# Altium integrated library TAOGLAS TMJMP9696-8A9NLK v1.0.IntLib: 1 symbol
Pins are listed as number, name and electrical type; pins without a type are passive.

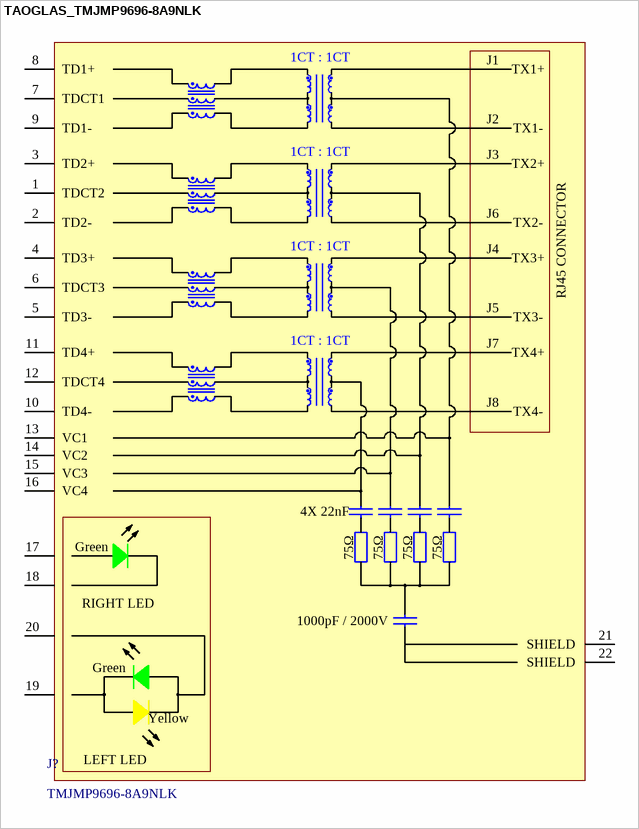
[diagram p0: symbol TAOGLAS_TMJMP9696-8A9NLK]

## TAOGLAS_TMJMP9696-8A9NLK
designator J?, comment TMJMP9696-8A9NLK
RJ45 connector with integrated magnetics 10G Base-T Single Port Tab-UP with right angle THT mount and LED; ComponentLibStatus: Created; MFG: Taoglas; Temp_High: +85C; Temp_Low: -40C
footprint TAOGLAS_TMJMP9696-8A9NLK (RJ45 connector with integrated magnetics 10G Base-T Single Port Tab-UP with right angle THT mount and LED)
pins: 1 TDCT2, 2 TD2-, 3 TD2+, 4 TD3+, 5 TD3-, 6 TDCT3, 7 TDCT1, 8 TD1+, 9 TD1-, 10 TD4-, 11 TD4+, 12 TDCT4, 13 VC1, 14 VC2, 15 VC3, 16 VC4, 17, 18, 19, 20, 21 SHIELD, 22 SHIELD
